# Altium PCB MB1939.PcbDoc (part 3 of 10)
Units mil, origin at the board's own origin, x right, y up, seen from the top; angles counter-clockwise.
Board outline 5910.64 x 4335.93 mil, 6 copper layers (Top Layer, l2_GND, L3_SIG, L4_VCC, L5_GND, Bottom Layer), stack 58.424 mil thick; 635 components, 489 nets, 2289 pads, 1388 vias.
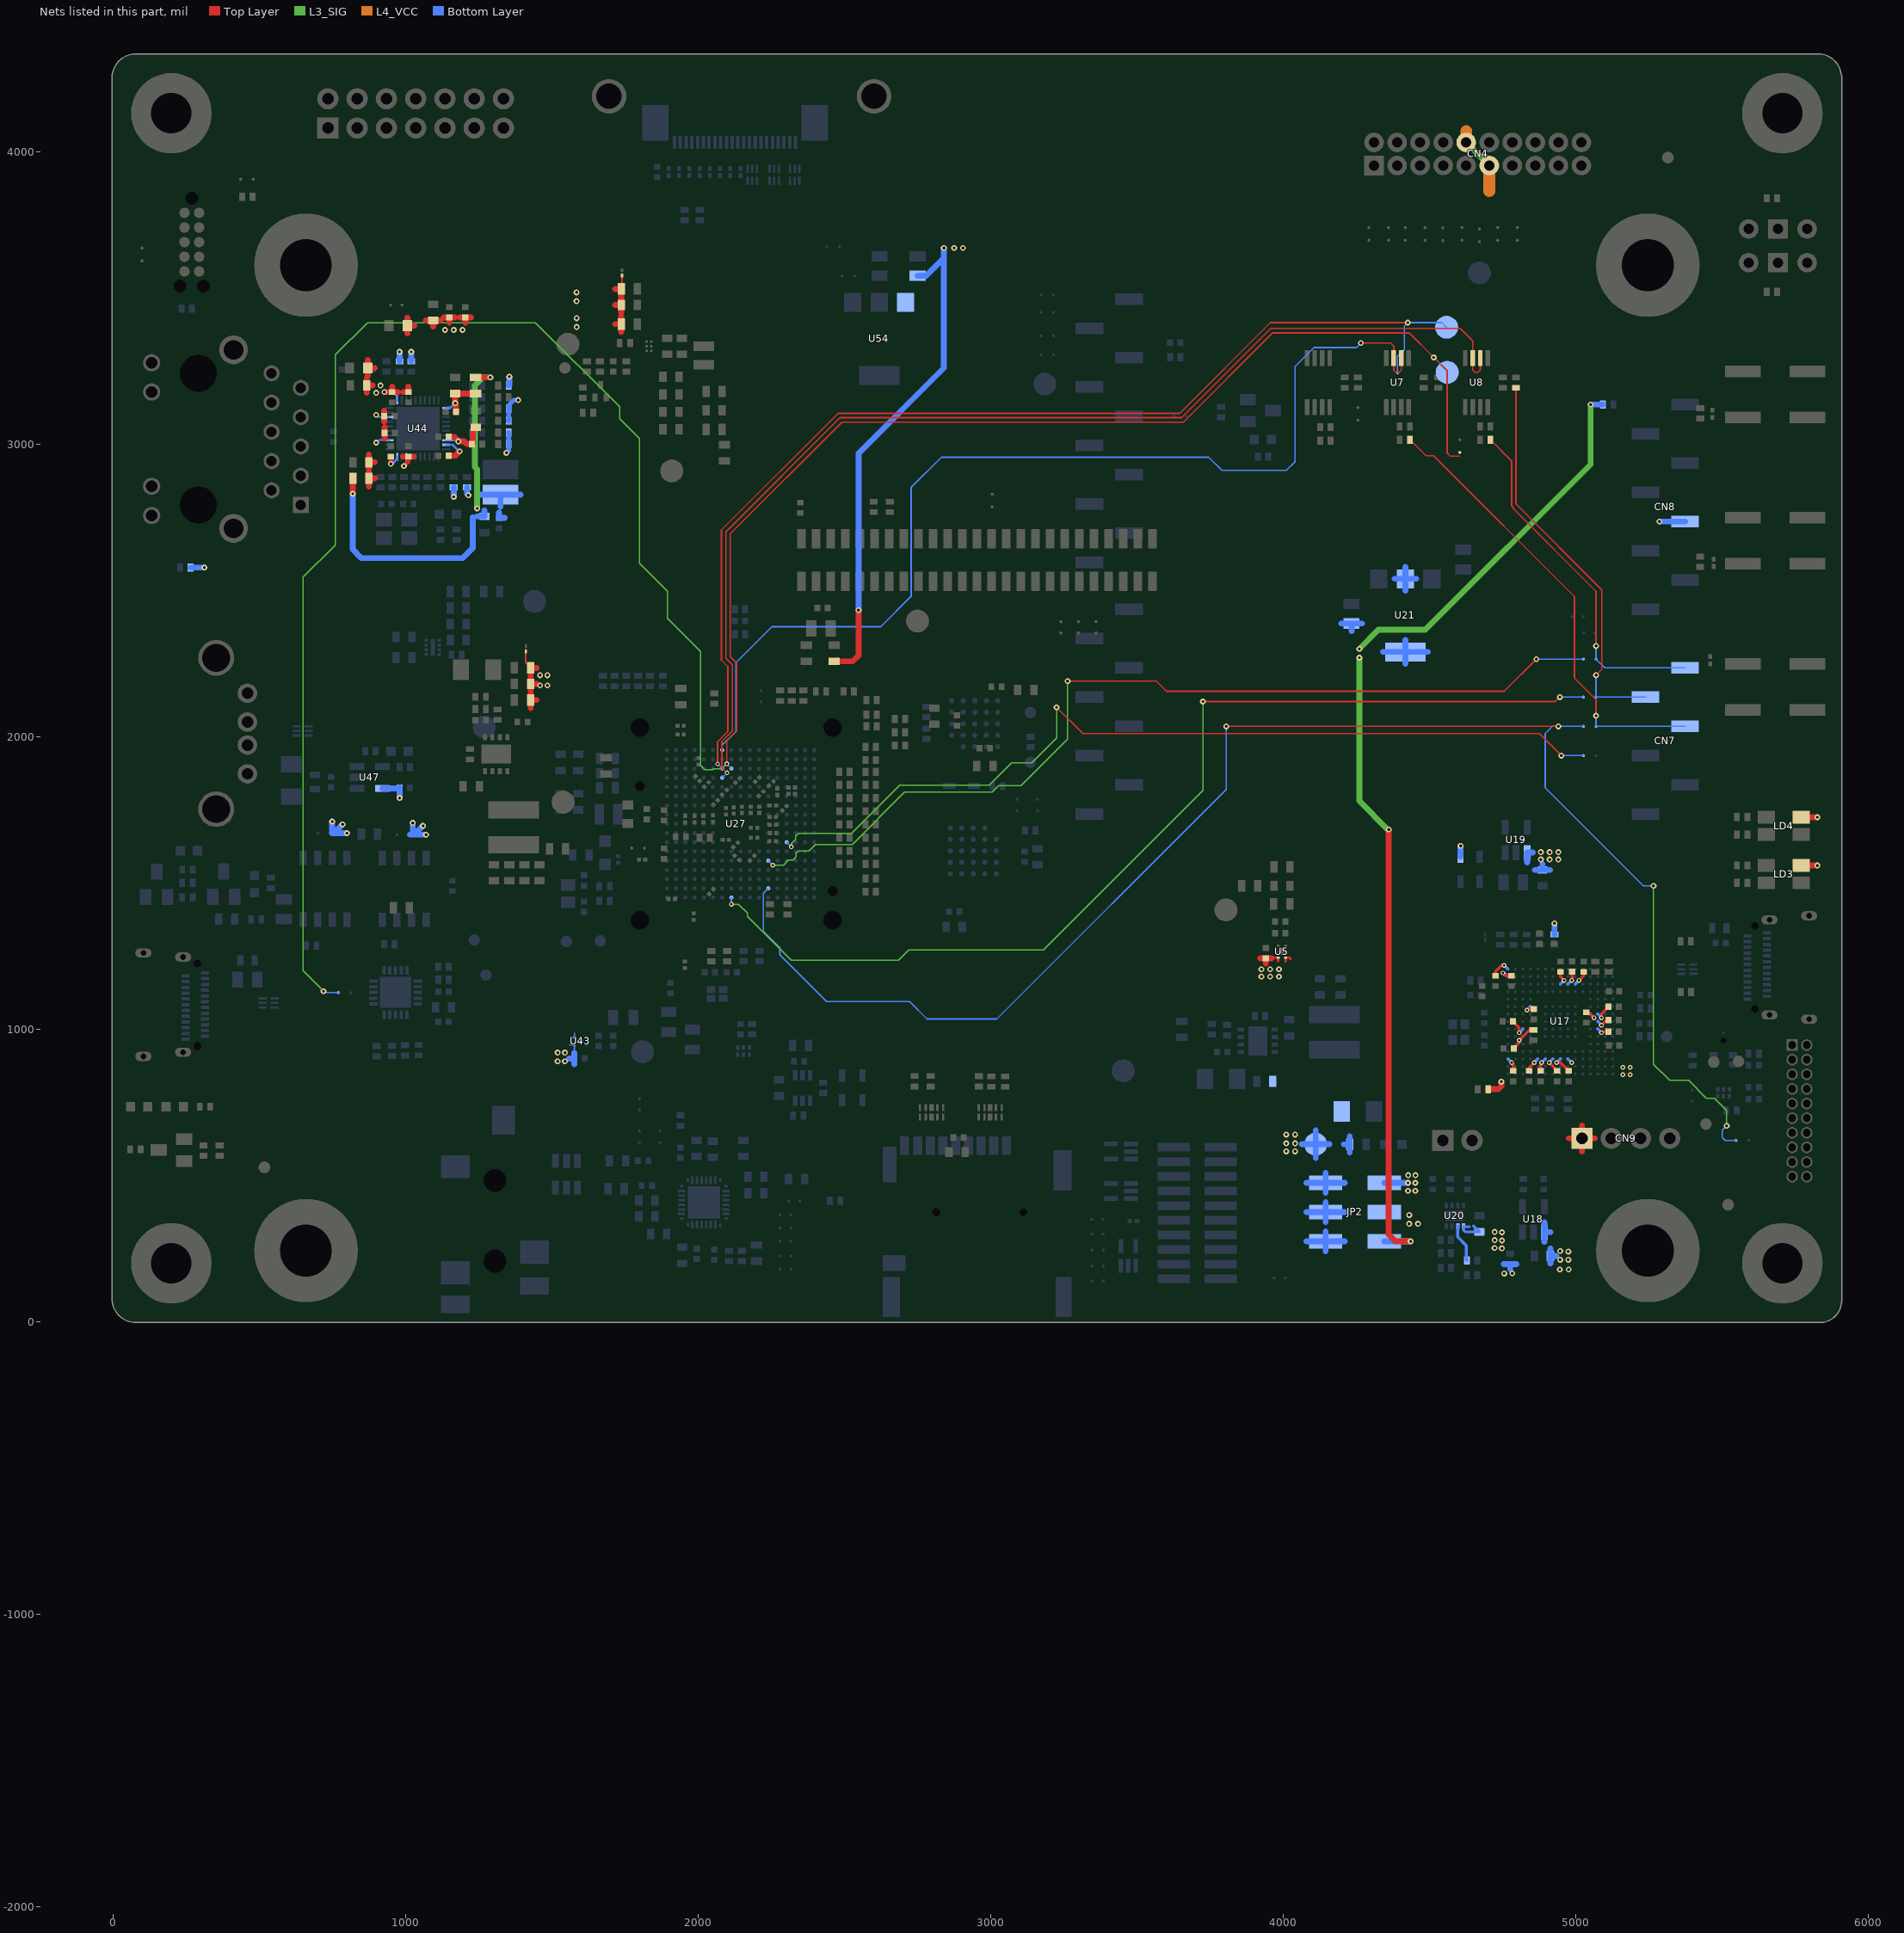
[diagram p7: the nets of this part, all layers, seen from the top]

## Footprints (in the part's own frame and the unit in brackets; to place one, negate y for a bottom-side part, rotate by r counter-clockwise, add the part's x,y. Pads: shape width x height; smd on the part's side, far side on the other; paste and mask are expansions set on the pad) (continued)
REG_XDFN4-EPAD_CASE-711AJ_1X1_H0P4_P065 [mm] "MCD-01613"
  rect 0.26x0.17 smd paste-10 mask-10: 1(-0.325,-0.515) 2(0.325,-0.515) 3(0.325,0.515) 4(-0.325,0.515)
  rect 0.52x0.52 smd rot 45 paste+0 mask+0.038: 5(0,0)
  Top Layer region: 0.455,-0.6 0.195,-0.6 0.195,-0.39 0.375,-0.21 0.455,-0.21
  Top Layer region: -0.455,-0.6 -0.195,-0.6 -0.195,-0.39 -0.375,-0.21 -0.455,-0.21
  Top Layer region: 0.455,0.6 0.195,0.6 0.195,0.39 0.375,0.21 0.455,0.21
  Top Layer region: -0.455,0.6 -0.195,0.6 -0.195,0.39 -0.375,0.21 -0.455,0.21
  silkscreen extent -0.63,-0.67 0.5,0.5, body extent -0.5,-0.5 0.5,0.5, height 0.44
SOLDER-BRIDGE_R0402-0R [mil] "MCD-01619"
  round 10 smd paste-393.7: 1(-17.72,0) 2(20.67,0)
  Top Layer region: -30.51,-13.78 -30.51,13.78 -8.37,13.78 -1.48,0 -8.37,-13.78
  Top Layer region: 1.48,13.78 8.37,0 1.48,-13.78 30.51,-13.78 30.51,13.78
  silkscreen extent -33,-17 33,17, body extent -20,-12 20,12, height 14
SOLDER-BRIDGE_R0603-0R [mil]
  round 10 smd paste-393.7: 1(-19.68,0) 2(23.62,0)
  Top Layer region: -5.91,19.69 13.78,0 -5.91,-19.68 47.24,-19.68 47.24,19.69 -5.91,19.69
  Top Layer region: -47.24,-19.68 -47.24,19.69 -15.75,19.69 3.94,0 -15.75,-19.68 -47.24,-19.68
  silkscreen extent -50,-23 50,23, body extent -36,-20 36,20, height 22
STICKER_BOARD_25X9 [mil] "Sticker to mention board CPN code"
  silkscreen extent -492,-177 492,177
STICKER_PRODUCT_25X9 [mil] "Sticker to mention board CPN code"
  silkscreen extent -492,-177 492,177
SWI_C&K_KSC321JLFS_BLACK [mm] "MCD-01799"
  rect 3.1x1 smd mask+0.05: 1(-2.8,2) 2(2.8,2) 3(-2.8,-2) 4(2.8,-2)
  silkscreen extent -3.25,-3.25 3.25,3.25, body extent -3.4,-3.25 3.4,3.25, height 3.5
SWI_C&K_KSC721JLFS_BLUE [mm] "MCD-01800"
  rect 3.1x1 smd mask+0.05: 1(-2.8,2) 2(2.8,2) 3(-2.8,-2) 4(2.8,-2)
  silkscreen extent -3.25,-3.25 3.25,3.25, body extent -3.4,-3.25 3.4,3.25, height 4.3
SWI_EAO_09-03290-01_EXTENDED_STRAIGHT_BLACK [mm]
  rect 1.7x1.7 hole 0.9 mask+0.05: 1(0,0)
  round 1.7 hole 0.9 mask+0.05: 2(0,-2.54) 3(0,2.54)
  silkscreen extent -1.25,-5 1.25,5, body extent -1.25,-5 1.25,5, height 7.9
TP_SMD_1MM [mm]
  round 1 smd paste-10 mask+0.05: 1(0,0)
  silkscreen extent -0.7,-0.7 0.7,0.7
TP_SMD_2MM [mm]
  round 2 smd paste-10 mask+0.05: 1(0,0)
  silkscreen extent -1.2,-1.2 1.2,1.2

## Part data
B1: library part MCD-01799, "Switch tactile, SPST-NO, 32V, 50mA, 6.2x6.2mm", Manufacturer=C&K, Manufacturer_HQ_COO=Unknown, Manufacturer_Part_Number=KSC321JLFS, Package=6.2x6.2mm
B2 B4: library part MCD-01800, "Switch tactile, SPST-NO, 32V, 50mA, 6.2x6.2mm", Manufacturer=C&K, Manufacturer_HQ_COO=Unknown, Manufacturer_Part_Number=KSC721JLFS, Package=6.2x6.2mm
C1 C2 C9 C14 C19 C21 C22 C23 C25 C26 C27 C42 C49 C53 C56 C62 C93 C135 C136 C170 C176 C177 C178 C179 C181 C182: library part MCD-00100, "Capacitor, MLCC, 22uF, 6V3, X5R, +/-20%, 0603, T=0.8mm", Manufacturer=MURATA, Manufacturer_Part_Number=GRM188R60J226MEA0J, Package=0603
C3 C4 C5 C6 C7 C8 C10 C11 C12 C13 C17 C18 C81 C83 C86 C87 C89 C90 C96 C97 C98 C99 C100 C101 C102 C104 C106 C107 C108 C109 C110 C111 C112 C113 C114 C117 C119 C130 C140 C142 C144 C149 C152 C159 C162 C164 C165 C180 C193 C194: library part MCD-00006, "Capacitor, MLCC, 100nF, 16V, X7R, +/-10%, 0402, T=0.5mm", Manufacturer=YAGEO, Manufacturer_Part_Number=CC0402KRX7R7BB104, Package=0402
C15 C138 C195 C201: library part MCD-00104, "Capacitor, MLCC, 220uF, 6V3, X5R, +/-20%, 1206, T=1.6mm", Manufacturer=MURATA, Manufacturer_Part_Number=GRM31CR60J227ME11, Package=1206
C16 C31 C32 C123 C124 C129 C137 C146 C183 C189: library part MCD-00099, "Capacitor, MLCC, 10uF, 10V, X5R, +/-10%, 0603, T=0.8mm", Manufacturer=MURATA, Manufacturer_Part_Number=GRM188R61A106KE69D, Package=0603
C20: library part MCD-01783, "Capacitor, MLCC, 22pF, 50V, NPO,+/-2%, 0402, T=0.5mm", Manufacturer=YAGEO, Manufacturer_Part_Number=CC0402GRNPO9BN220, Package=0402
C24 C92 C94 C95 C118 C139 C145 C161 C171 C172 C173: library part MCD-00095, "Capacitor, MLCC, 1uF, 25V, X5R, +/-10%, 0402, T=0.5mm", Manufacturer=MURATA, Manufacturer_Part_Number=GRM155R61E105KA12, Package=0402
C28 C36 C39 C40 C46 C47 C48 C50 C52 C54 C55 C58 C59 C64 C66 C67 C71 C72 C73 C74 C75 C76 C77 C78 C79 C80 C169: library part MCD-01535, "Capacitor, MLCC,100nF, 10V, X5R, +/-10%, 0201, T=0.3mm", Manufacturer=MURATA, Manufacturer_Part_Number=GRM033R61A104KE15, Package=0201
C29 C35: library part MCD-01355, "Capacitor, MLCC, 10uF, 4V, X5R, +/-20%, 0402, T=0.5mm", Manufacturer=MURATA, Manufacturer_Part_Number=GRM155R60G106ME44, Package=0402
C30 C120: library part MCD-00205, "Capacitor, MLCC, 100pF, 50V, NPO, +/-5%, 0402, T=0.5mm", Manufacturer=YAGEO, Manufacturer_Part_Number=CC0402JRNPO9BN101, Package=0402
C33 C198: library part MCD-00011, "Capacitor, MLCC, 10nF, 16V, X7R, +/-10%, 0402, T=0.5mm", Manufacturer=YAGEO, Manufacturer_Part_Number=CC0402KRX7R7BB103, Package=0402
C34: library part MCD-01356, "Capacitor, MLCC, 4.7uF, 6V3, X5R, +/-20%, 0402, T=0.5mm", Manufacturer=MURATA, Manufacturer_Part_Number=GRM155R60J475ME47, Package=0402
C37: library part MCD-02620, "Capacitor, MLCC, 2.2nF, 50V, X7R, +/-10%, 0402, T=0.5mm", Manufacturer=YAGEO, Manufacturer_Part_Number=CC0402KRX7R9BB222, Package=0402
C38 C41 C43 C44 C45 C51 C57 C60 C61 C63 C65 C68 C69 C70: library part MCD-02377, "Capacitor, MLCC, 1uF, 6.3V, X5R, +/-20%, 0201, T=0,3mm", Manufacturer=MURATA, Manufacturer_Part_Number=GRM033R60J105MEA2, Package=0201
C82 C131 C134 C199 C200: library part MCD-00014, "Capacitor, MLCC, 10uF, 25V, X5R, +/-10%, 0805, T=0.85mm", Manufacturer=YAGEO, Manufacturer_Part_Number=CC0805KRX5R8BB106, Package=0805
C84 C85 C88 C91 C141 C143 C147 C150 C158 C168: library part MCD-00009, "Capacitor, MLCC, 4.7uF, 16V, X5R, +/-10%, 0603, T=0.8mm", Manufacturer=YAGEO, Manufacturer_Part_Number=CC0603KRX5R7BB475, Package=0603
C103 C105 C133 C184: library part MCD-02198, "Capacitor, MLCC, 10nF, 50V, X7R, +/-10%, 0402, T=0.5mm", Manufacturer=YAGEO, Manufacturer_Part_Number=CC0402KRX7R9BB103, Package=0402
C115 C116 C121: library part MCD-02606, "Capacitor, MLCC, 2.2uF, 6.3V, X5R, +/-10%, 0402, T=0.5mm", Manufacturer=YAGEO, Manufacturer_Part_Number=CC0402KRX5R5BB225, Package=0402
C122: library part MCD-00016, "Capacitor, MLCC, 20pF, 50V, NPO, +/- 5%, 0402, T=0.5mm", Manufacturer=YAGEO, Manufacturer_Part_Number=CC0402JRNPO9BN200, Package=0402
C125 C132 C190: library part MCD-02355, "Capacitor, MLCC, 100nF, 25V, X7R, +/-10%, 0402, T=0.5mm", Manufacturer="WALSIN TECHNOLOGY CORPORATION", Manufacturer_Part_Number=0402B104K250CT, Package=0402
C126 C197: library part MCD-02372, "Capacitor, MLCC, 2.2uF, 25V, X7R, +/-10%, 0805, T=1,25mm", Manufacturer=MURATA, Manufacturer_Part_Number=GRM21BR71E225KE11L, Package=0805
C127 C128: library part MCD-01374, "Capacitor, MLCC, 5.6pF, 50V, NPO, +/-0.1pF, 0402, T=0.5mm", Manufacturer=YAGEO, Manufacturer_Part_Number=CC0402BRNPO9BN5R6, Package=0402
C148 C160 C163 C167: library part MCD-00012, "Capacitor, MLCC, 2.2uF, 10V, X5R, +/- 10%, 0603, T=0.8mm", Manufacturer=YAGEO, Manufacturer_Part_Number=CC0603KRX5R6BB225, Package=0603
C151: library part MCD-00015, "Capacitor, MLCC, 10pF, 50V, NPO, +/-5%, 0402, T=0.5mm", Manufacturer=YAGEO, Manufacturer_Part_Number=CC0402JRNPO9BN100, Package=0402
C153 C155: library part MCD-01932, "Capacitor, MLCC, 8.2pF, 50V, NPO, +/-0.25pF, 0402, T=0.5mm", Manufacturer=YAGEO, Manufacturer_Part_Number=CC0402CRNPO9BN8R2, Package=0402
C154 C156: library part MCD-00010, "Capacitor, MLCC, 1uF, 16V, X5R, +/-10%, 0603, T=0.8mm", Manufacturer=YAGEO, Manufacturer_Part_Number=CC0603KRX5R7BB105, Package=0603
C174 C175: library part MCD-01775, "Capacitor, MLCC, 3.3pF, 50V, NPO, +/-0.1pF, 0402, T=0.5mm", Manufacturer=YAGEO, Manufacturer_Part_Number=CC0402BRNPO9BN3R3, Package=0402
C185: library part MCD-01099, "Capacitor, MLCC, 100nF, 50V, X7R, +/-10%, 0603, T=0.8mm", Manufacturer=YAGEO, Manufacturer_Part_Number=CC0603KRX7R9BB104, Package=0603
C186 C187: library part MCD-01579, "Capacitor, MLCC, 330pF, 50V, NPO, +/-5%, 0402, T=0.5mm", Manufacturer=YAGEO, Manufacturer_Part_Number=CC0402JRNPO9BN331, Package=0402
C188 C191: library part MCD-01781, "Capacitor, MLCC, 6.8pF, 50V, NPO, +/-0.1pF, 0402, T=0.5mm", Manufacturer=YAGEO, Manufacturer_Part_Number=CC0402BRNPO9BN6R8, Package=0402
C196: library part MCD-01549, "Capacitor, MLCC, 1nF, 50V, X7R,+/-10%, 0805, T=0.6mm", Manufacturer=YAGEO, Manufacturer_Part_Number=CC0805KRX7R9BB102, Package=0805
CN1: library part MCD-00031, "Header_Plug-of-nails, 5x2, 1.27mm, No legs", Manufacturer=N/A
CN2: library part MCD-02123, "Header, 7x2, 2.54mm, VR, TH, T=5.84mm/2.54mm", Manufacturer=SAMTEC, Manufacturer_Part_Number=TSW-107-07-G-D
CN3: library part MCD-01222, "Socket, 25x2, 1.27mm, SMD, VR, T=4.55mm", Manufacturer=SAMTEC, Manufacturer_Part_Number=FLE-125-01-G-DV
CN4: library part MCD-00309, "Socket, 10x2, 2mm, RA, TH, T=6.35mm/2.29mm", Manufacturer=SAMTEC, Manufacturer_Part_Number=SQT-110-01-F-D-RA
CN5: library part MCD-00147, "Socket, 10x2, 1.27mm, VR, TH, T=4.30mm/2.40mm", Manufacturer="AMPHENOL CS", Manufacturer_Part_Number=20021311-00020T4LF
CN6 CN18: library part MCD-03232, "USB_TypeC, 24 pins, RA, SMD, T=2.96mm", Manufacturer="AMPHENOL CS", Manufacturer_Part_Number=12401826E412A
CN7: library part MCD-00299, "Socket, 6x1, 2.54mm, VR, SMD, T=9.78mm", Manufacturer=SAMTEC, Manufacturer_Part_Number=SSW-106-22-L-S-VS
CN8 CN11: library part MCD-00300, "Socket, 8x1, 2.54mm, VR, SMD, T=9.78mm", Manufacturer=SAMTEC, Manufacturer_Part_Number=SSW-108-22-L-S-VS
CN9: library part MCD-00029, "Header, 4x1, 2.54mm, VR, TH, T=5.84mm/2.54mm", Manufacturer=SAMTEC, Manufacturer_Part_Number=TSW-104-07-G-S
CN10: library part MCD-00557, "Header, 10x2, 1.27mm, VR, SMD, T=3.05mm", Manufacturer=SAMTEC, Manufacturer_Part_Number=FTSH-110-01-L-DV
CN12: library part MCD-00301, "Socket, 10x1, 2.54mm, VR, SMD, T=9.78mm", Manufacturer=SAMTEC, Manufacturer_Part_Number=SSW-110-22-L-S-VS
CN13: library part MCD-00023, "Connector_uSD Card, Reversed-Type, Mnt Push-Push", Manufacturer=YAMAICHI, Manufacturer_Part_Number=PJS008-2003-1
CN14: library part MCD-03600, "Socket_FFC/FPC, 22pins, 0.5mm, RA, SMD, T=2mm", Manufacturer="TE CONNECTIVITY"
CN15: library part MCD-00263, "Jack_ Socket-Stereo, 3.5mm, 4 pins, RA, SMD, T=5mm", Manufacturer=QIAOD, Manufacturer_Part_Number=PJ-3028B-4P
CN16: library part MCD-01129, "Connector_RJ45, With Gigabit magnetics Mag and LED, 10pins, 2.54mm, VR, TH, T= 13.84mm", Manufacturer="YUAN DEAN SCIENTIFIC", Manufacturer_Part_Number=48F-01GYDXNL, Package=13.84x21.59mm
CN17: library part MCD-01475, "USB_TypeA, RA, TH, T= 7.73mm (USB certified)", Manufacturer=MOLEX, Manufacturer_Part_Number=67643-3911
D1 D2: library part MCD-03011, "Diode, Schottky, 0V54, 1A, 23V, SOD-323", Manufacturer=STMICROELECTRONICS, Manufacturer_Part_Number=BAT20JFILM, Package=SOD-323
D4 D5 D6 D7: library part MCD-00034, "Diode, Schottky, 0V53, 1A, 10V, SOD323", Manufacturer=STMICROELECTRONICS, Manufacturer_HQ_COO=EU, Package=SOD323
H1 H2 H7 H8: library part MCD-00328, "POSITION HOLE, C7D3R5", Manufacturer=N/A, Manufacturer_HQ_COO=Unknown
H3 H4 H5 H6: library part MCD-01612, "POSITION HOLE, C9D4R5", Manufacturer=N/A
HW1: library part MCD-00547, "Sticker product, 25x9mm", Manufacturer=N/A, Manufacturer_HQ_COO=Unknown
HW2: library part MCD-00235, "Sticker Board, 25x9mm", Manufacturer=N/A
JP1: library part MCD-00045, "Header, 2x1, 2.54mm, VR, TH, T=5.84mm/2.54mm", Manufacturer=SAMTEC, Manufacturer_Part_Number=TSW-102-07-G-S
JP2: library part MCD-03177, "Header, 3x2, 2.54mm, VR, SMD, T=9,65mm", Manufacturer=SAMTEC, Manufacturer_Part_Number=TSM-103-01-G-DV
L1 L2: library part MCD-00094, "Ferrite bead, 100R @ 100MHz, +/-25%, 2000mA, 0R045, 0603, T=0.5mm", Manufacturer=MURATA, Manufacturer_Part_Number=BLM18EG101TN1, Package=0603
L3 L6: library part MCD-02242, "Inductor, 2.2uH, +/-30%, 3,83A, 0R023, 4x4mm, T=2.5mm", Manufacturer="WURTH ELEKTRONIK", Manufacturer_Part_Number=74404043022A, Package=4x4mm
L4: library part MCD-03222, "Inductor, 2.2nH, +/-0.5nH, Irat=1.4Amax, 0R018, 0603, T=1mm, Qmin=25", Manufacturer=MURATA, Manufacturer_Part_Number=LQW18AN2N2D10D, Package=0603
L5: library part MCD-02477, "Inductor, 240nH, +/-20%, 4.4A, 23mR, 0806, T=1.2mm", Manufacturer=MURATA, Manufacturer_Part_Number=DFE201612P-R24M{}P2, Package=0806
L7: library part MCD-01491, "Inductor, 1uH, +/-20%, Itemp= 2700mA, Isat= 3300mA, 0R054, 0806, T=1mm", Manufacturer=MURATA, Manufacturer_Part_Number=DFE201612P-1R0M, Package=0806
L8: library part MCD-03956, "Ferrite bead, 18R @ 100MHz, 750mA, 0R004, 0603, T=1mm", Manufacturer="TAIYO YUDEN", Manufacturer_Part_Number=LSMCA160808T180NGR, Package=0603
LD1 LD5 LD6 LD7 LD9: library part MCD-00588, "LED, Green, 2V, 20mA, 0603", Manufacturer="OSRAM OPTO SEMICONDUCTORS", Manufacturer_Part_Number="LG Q396-PS-35", Package=0603
LD2 LD8 LD10: library part MCD-00587, "LED, Red, 2V, 20mA, 0603", Manufacturer=VISHAY, Manufacturer_Part_Number=VLMS1300-GS08, Package=0603
LD3 LD4: library part MCD-02631, "LED Bicolor, Red/Green, 2V, 20mA, 4-PLCC", Manufacturer="WURTH ELEKTRONIK", Manufacturer_Part_Number=150141SV73110, Package=4-PLCC
LE1: library part MCD-00048, "Inductor, 4.7uH, +/-30%, 1A, 180mR, 1210, T=1.7mm", Manufacturer=MURATA, Manufacturer_Part_Number=LQH32PN4R7NN0L, Package=1210
LNK1 LNK2 LNK3: library part MCD-02777, "Track link on PCB 200um width for layout routing", Manufacturer=N/A
Q1 Q5 Q6: library part MCD-00073, "Transistor, NPN, 40V, 800mA, SOT23", Manufacturer="ON SEMICONDUCTOR", Manufacturer_Part_Number=BSR14, Package=SOT23
Q2: library part MCD-01969, "Transistor, MOSFET, N-CH, 60V, 265mA, SOT23-3", Manufacturer=NEXPERIA, Manufacturer_Part_Number=BSN20BK, Package=SOT23-3
Q3 Q4: library part MCD-02152, "Transistor, MOSFET, N-CH, 30V, 40A, PowerFLAT-8", Manufacturer=STMICROELECTRONICS, Manufacturer_HQ_COO=EU, Package=PowerFLAT-8
Q7: library part MCD-02221, "Transistor, MOSFET, N-CH, 20V, 530mA, SC89-3", Manufacturer=VISHAY, Manufacturer_Part_Number=Si1062X, Package=SC89-3
R1 R8 R99 R101 R131 R217: library part MCD-00062, "Resistor, 330R, 0402, +/-1%, 1/16W", Manufacturer=YAGEO, Manufacturer_Part_Number=RC0402FR-07330RL, Package=0402
R2 R211: library part MCD-00507, "Resistor, 680R, 0402, +/-1%, 1/16W", Manufacturer=YAGEO, Manufacturer_Part_Number=RC0402FR-07680RL, Package=0402
R3 R96 R97 R118 R120 R125 R150 R201 R210 R215: library part MCD-00059, "Resistor, 100K, 0402, +/-1%, 1/16W", Manufacturer=YAGEO, Manufacturer_Part_Number=RC0402FR-07100KL, Package=0402
R4 R73 R74 R76 R77 R213 R216: library part MCD-00063, "Resistor, 47K, 0402, +/-1%, 1/16W", Manufacturer=YAGEO, Manufacturer_Part_Number=RC0402FR-0747KL, Package=0402
R5 R26 R75 R93 R102 R103 R105 R106 R115 R119 R121 R138 R139 R140 R142 R143 R144 R151 R197 R207 R221 R222 R224 R225: library part MCD-00053, "Resistor, 10K, 0402, +/-1%, 1/16W", Manufacturer=YAGEO, Manufacturer_Part_Number=RC0402FR-0710KL, Package=0402
R6 R9 R19 R23 R41 R43 R130 R145 R147 R199: library part MCD-00056, "Resistor, 0R, 0603, +/-5%, 1/10W", Manufacturer=YAGEO, Manufacturer_Part_Number=RC0603JR-070RL, Package=0603
R7: library part MCD-02232, "Resistor, 22mR, 0603, +/-1%, 1/3W", Manufacturer=PANASONIC, Manufacturer_Part_Number=ERJ-3BWFR022V, Package=0603
R10 R133 R192: library part MCD-00435, "Resistor, 24K, 0402, +/-1%, 1/16W", Manufacturer=YAGEO, Manufacturer_Part_Number=RC0402FR-0724KL, Package=0402
R11: library part MCD-02979, "Resistor, 30K, 0402, +/-0.1%, 1/16W, +/-25ppm/°C", Manufacturer=YAGEO, Manufacturer_Part_Number=RT0402BRD0730KL, Package=0402
R12 R25 R37 R39 R40 R42 R44 R45 R46 R47 R48 R49 R50 R51 R52 R53 R54 R55 R56 R57 R58 R59 R60 R61 R62 R63 R64 R65 R66 R67 R68 R69 R70 R71 R72 R104 R112 R116 R117 R137 R141 R146 R154 R155 R170 R171 R189 R198 R202 R205 R206 R226 R227: library part MCD-00052, "Resistor, 0R, 0402, +/-5%, 1/16W", Manufacturer=YAGEO, Manufacturer_Part_Number=RC0402JR-070RL, Package=0402
R13 R14 R15 R16 R17 R18 R174 R175 R176 R177 R178 R191 R194 R195: library part MCD-00065, "Resistor, 4K7, 0402, +/-1%, 1/16W", Manufacturer=YAGEO, Manufacturer_Part_Number=RC0402FR-074K7L, Package=0402
R20 R24 R188: library part MCD-03197, "Resistor, 330mR, 0603, +/-1%, 1/5W", Manufacturer=YAGEO, Manufacturer_Part_Number=PT0603FR-7W0R33L, Package=0603
R21 R22 R27 R30 R31 R78 R79 R136 R167 R173 R179 R187 R209: library part MCD-00181, "Resistor, 0R, 0603, +/- 0.5mR, 1/4W", Manufacturer="ROHM SEMICONDUCTOR", Manufacturer_Part_Number=PMR03EZPJ000, Package=0603
R28: library part MCD-00493, "Resistor, 56K, 0402, +/-1%, 1/16W", Manufacturer=YAGEO, Manufacturer_Part_Number=RC0402FR-0756KL, Package=0402
R29: library part MCD-00405, "Resistor, 160K, 0402, +/-1%, 1/16W", Manufacturer=YAGEO, Manufacturer_Part_Number=RC0402FR-07160KL, Package=0402
R32 R33 R34: library part MCD-00417, "Resistor, 200R, 0402, +/-1%, 1/16W", Manufacturer=YAGEO, Manufacturer_Part_Number=RC0402FR-07200RL, Package=0402
R35 R168: library part MCD-02233, "Resistor, 50mR, 0603, +/-1%, 1/3W", Manufacturer=PANASONIC, Manufacturer_Part_Number=ERJ-3BWFR050V, Package=0603
R36 R38 R149 R153 R186 R200 R204: library part MCD-00068, "Resistor, 1K5, 0402, +/-1%, 1/16W", Manufacturer=YAGEO, Manufacturer_Part_Number=RC0402FR-071K5L, Package=0402
R80: library part MCD-03198, "Resistor, 750mR, 0603, +/-1%, 1/5W", Manufacturer=YAGEO, Manufacturer_Part_Number=PT0603FR-7W0R75L, Package=0603
R81 R84 R85 R88 R89 R92: library part MCD-00483, "Resistor, 470K, 0402, +/-1%, 1/16W", Manufacturer=YAGEO, Manufacturer_Part_Number=RC0402FR-07470KL, Package=0402
R82 R83 R86 R87 R90 R91: library part MCD-00495, "Resistor, 560K, 0402, +/-1%, 1/16W", Manufacturer=YAGEO, Manufacturer_Part_Number=RC0402FR-07560KL, Package=0402
R94 R95 R114 R122: library part MCD-00455, "Resistor, 33R, 0402, +/-1%, 1/16W", Manufacturer=YAGEO, Manufacturer_Part_Number=RC0402FR-0733RL, Package=0402
R98 R100: library part MCD-02665, "Resistor, 1K, 0402, +/-0.1%, 1/16W, +/-25ppm/°C", Manufacturer=YAGEO, Manufacturer_Part_Number=RT0402BRD071KL, Package=0402
R107 R108 R113: library part MCD-00333, "Resistor, 5K1, 0402, +/-1%, 1/16W", Manufacturer=YAGEO, Manufacturer_Part_Number=RC0402FR-075K1L, Package=0402
R109 R124: library part MCD-00185, "Resistor, 3K, 0402, +/-1%, 1/16W", Manufacturer=YAGEO, Manufacturer_Part_Number=RC0402FR-073KL, Package=0402
R110: library part MCD-00067, "Resistor, 100R, 0402, +/- 1%, 1/16W", Manufacturer=YAGEO, Manufacturer_Part_Number=RC0402FR-07100RL, Package=0402
R111: library part MCD-00061, "Resistor, 1K, 0402, +/-1%,1/16W", Manufacturer=YAGEO, Manufacturer_Part_Number=RC0402FR-071KL, Package=0402
R123 R128: library part MCD-02455, "Resistor, 3K9, 0402, +/-1%, 1/16W, +/-100ppm/°C", Manufacturer=YAGEO, Manufacturer_Part_Number=RC0402FR-073K9L, Package=0402
R126: library part MCD-00381, "Resistor, 1K3, 0402, +/-1%, 1/16W", Manufacturer=YAGEO, Manufacturer_Part_Number=RC0402FR-071K3L, Package=0402
R127: library part MCD-00409, "Resistor, 1K8, 0402, +/-1%, 1/16W", Manufacturer=YAGEO, Manufacturer_Part_Number=RC0402FR-071K8L, Package=0402
R129: library part MCD-00528, "Resistor, 820R, 0603, +/-1%, 1/10W", Manufacturer=YAGEO, Manufacturer_Part_Number=RC0603FR-07820RL, Package=0603
R132: library part MCD-00489, "Resistor, 560R, 0402, +/-1%, 1/16W", Manufacturer=YAGEO, Manufacturer_Part_Number=RC0402FR-07560RL, Package=0402
R134 R223: library part MCD-00182, "Resistor, 1M, 0402, +/-1%, 1/16W", Manufacturer=YAGEO, Manufacturer_Part_Number=RC0402FR-071ML, Package=0402
R135: library part MCD-00521, "Resistor, 75K, 0402, +/-1%, 1/16W", Manufacturer=YAGEO, Manufacturer_Part_Number=RC0402FR-0775KL, Package=0402
R148 R159 R163: library part MCD-00179, "Resistor, 0R, 0805, +/-5%, 1/8W", Manufacturer=YAGEO, Manufacturer_Part_Number=RC0805JR-070RL, Package=0805
R152: library part MCD-02335, "Resistor, 140K, 0402, +/-1%, 1/16W", Manufacturer=YAGEO, Manufacturer_Part_Number=RC0402FR-07140KL, Package=0402
R156: library part MCD-00057, "Resistor, 2K2, 0402, +/-1%, 1/16W", Manufacturer=YAGEO, Manufacturer_Part_Number=RC0402FR-072K2L, Package=0402
R157: library part MCD-04136, "Resistor, 422K, 0402, +/-1%, 1/16W", Manufacturer=YAGEO, Manufacturer_Part_Number=RC0402FR-07422KL, Package=0402
R158: library part MCD-00165, "Resistor, 150K, 0402, +/-1%, 1/16W", Manufacturer=YAGEO, Manufacturer_Part_Number=RC0402FR-07150KL, Package=0402
R160 R161 R162 R166 R169 R172 R180 R181 R182 R183 R184 R185 R196 R203: library part MCD-00189, "Resistor, 22R, 0402, +/-1%, 1/16W", Manufacturer=YAGEO, Manufacturer_Part_Number=RC0402FR-0722RL, Package=0402
R164 R165: library part MCD-00345, "Resistor, 20R, 0603, +/-1%, 1/10W", Manufacturer=YAGEO, Manufacturer_Part_Number=RC0603FR-0720RL, Package=0603
R190 R218 R219: library part MCD-00064, "Resistor, 510R, 0402, +/-1%, 1/16W", Manufacturer=YAGEO, Manufacturer_Part_Number=RC0402FR-07510RL, Package=0402
R193: library part MCD-02265, "Resistor,100K,0402,0.5%,1/16W", Manufacturer=YAGEO, Manufacturer_Part_Number=RC0402DR-07100KL, Package=0402
R208: library part MCD-00183, "Resistor, 2K49, 0402, +/-1%, 1/16W", Manufacturer=YAGEO, Manufacturer_Part_Number=RC0402FR-072K49L, Package=0402
R212: library part MCD-00441, "Resistor, 270R, 0402, +/-1%, 1/16W", Manufacturer=YAGEO, Manufacturer_Part_Number=RC0402FR-07270RL, Package=0402
R214: library part MCD-00430, "Resistor, 22K, 0603, +/-1%, 1/10W", Manufacturer=YAGEO, Manufacturer_Part_Number=RC0603FR-0722KL, Package=0603
R220: library part MCD-03930, "Resistor, 2R, 0402, +/-1%, 1/16W", Manufacturer=YAGEO, Manufacturer_Part_Number=RC0402FR-072RL, Package=0402
R228 R229: library part MCD-00387, "Resistor, 1M3, 0402, +/-1%, 1/16W", Manufacturer=YAGEO, Manufacturer_Part_Number=RC0402FR-071M3L, Package=0402
SB1 SB2 SB4 SB5 SB9 SB10 SB11 SB12 SB13 SB14 SB15 SB16 SB17 SB18 SB20 SB21 SB22 SB23 SB25 SB31 SB32 SB33 SB34 SB41 SB45 SB46 SB47 SB48 SB49 SB51 SB53: library part MCD-00071, "Resistor, 0R, SB0603, 5%, 0.1W", Manufacturer=YAGEO, Manufacturer_HQ_COO=Unknown, Manufacturer_Part_Number=RC0603JR-070RL, Package=0603
SB3 SB6 SB7 SB8 SB19 SB26 SB27 SB28 SB29 SB30 SB35 SB36 SB37 SB38 SB39 SB40 SB42 SB43 SB44 SB54 SB55 SB56 SB57 SB58 SB59: library part MCD-01618, "Resistor, 0R, SB0402, 5%, 0.063W", Manufacturer=YAGEO, Manufacturer_Part_Number=RC0402JR-070RL, Package=0402
SW1 SW2: library part MCD-00566, "Switch slide, SPDT, 24V, 500mA, 2.5x10mm", Manufacturer=EAO, Manufacturer_HQ_COO=Unknown, Manufacturer_Part_Number=09.03290.01, Package=2.5x10mm
TP1 TP3 TP4 TP5 TP10 TP11 TP12 TP13 TP14 TP15 TP16 TP17 TP21 TP22: library part MCD-00177, "Test Point, SMD, 2mm", Manufacturer=N/A
TP2 TP6 TP7 TP8 TP9 TP18 TP19 TP20 TP23 TP24 TP25: library part MCD-00074, "Test Point, SMD, 1mm", Manufacturer=N/A, Manufacturer_HQ_COO=Unknown
U1 U22: library part MCD-02243, "Regulator, 3A, DC step-down switching", Manufacturer=STMICROELECTRONICS, Manufacturer_HQ_COO=EU, Package=VFDFPN-8
U2: library part MCD-02469, "IC, 2V4 to 5V5 Input, Tiny 6-pin, 3A, Step-Down converter in 1.2x0.8mm wafer chip scale package and suitable for embedding", Manufacturer="TEXAS INSTRUMENTS", Package=WCSP-6
U3 U4: library part MCD-00667, "Diode, ESD protection, 3V6, 100nA, 5V8, uQFN-10", Manufacturer=STMICROELECTRONICS, Manufacturer_HQ_COO=EU, Package=uQFN-10
U5: library part MCD-02222, "LDO, 200mA, Very low quiescent current linear regulator IC", Manufacturer=STMICROELECTRONICS, Manufacturer_HQ_COO=EU, Manufacturer_Part_Number=LD39020ADTPU33R, Package=DFN-4
U6 U7 U8: library part MCD-00325, "Operational Amplifier, Single/dual/quad rail-to-rail input/output, 5V5, 400KHz", Manufacturer=STMICROELECTRONICS, Manufacturer_HQ_COO=EU, Package=miniSO-8
U9 U10 U12 U33 U35 U36 U37 U38 U39 U40 U41 U53: library part MCD-00170, "Diode, ESD TVS, 3V, 100nA, 8V, ST0201", Manufacturer=STMICROELECTRONICS, Manufacturer_HQ_COO=EU, Manufacturer_Part_Number=ESDALC6V1-1U2, Package=ST0201
U13: library part MCD-02122, "MEMS, Audio sensor Multi performance mode digital microphone", Manufacturer=STMICROELECTRONICS, Manufacturer_HQ_COO=EU, Manufacturer_Part_Number=MP23DB01HPTR, Package=RHLGA-5
U14 U32: library part MCD-02386, "Analog Switch, Low-ohmic single-pole double-throw analog switch", Manufacturer=NXP, Manufacturer_Part_Number=NX3L1T3157GMZ, Package=SOT886-6
U15 U29 U30 U31 U49 U51: library part MCD-03060, "IC, ESD protection and Common Filter High Speed serial Interfaces, 10.7 GHz", Manufacturer=STMICROELECTRONICS, Package=uQFN-6
U16 U50: library part MCD-01207, "Diode, ESD TVS, 22V, 200nA, 25V8, QFN1610", Manufacturer=STMICROELECTRONICS, Manufacturer_HQ_COO=EU, Manufacturer_Part_Number=ESDA25P35-1U1M, Package=QFN1610
U17: library part MCD-03851, "MCU, ARM Cortex-M7 32-bit, 512KB Flash, 276KB RAM, With Crypto", Manufacturer=STMICROELECTRONICS, Manufacturer_HQ_COO=EU, Manufacturer_Part_Number=STM32F723IEK6, Package=BGA-176
U18 U47: library part MCD-00159, "IC, Enhanced single channel power switches", Manufacturer=STMICROELECTRONICS, Package=SOT23-5
U19: library part MCD-02514, "LDO, 300mA, 28V, Low-dropout voltage, with 5uA quiescent current", Manufacturer=STMICROELECTRONICS, Package=SOT23-5
U20: library part MCD-02532, "IC, 2V7 to 18V, 4A, 34mR, eFuse with fast overvoltage protection", Manufacturer="TEXAS INSTRUMENTS", Package=WSON-8
U21: library part MCD-00088, "LDO, Adjustable and fixed low drop positive voltage regulator", Manufacturer=STMICROELECTRONICS, Manufacturer_HQ_COO=EU, Package=SOT223-4
U23 U24 U52: library part MCD-00136, "Diode, ESD Transil, 3V, 1uA, 7V2, SOT323-5", Manufacturer=STMICROELECTRONICS, Manufacturer_HQ_COO=EU, Package=SOT323-5
U25: library part MCD-02601, "Memory, Serial NOR Flash, 1V8, 1Gbit, 200MHz, BGA-24", Manufacturer=MACRONIX, Manufacturer_HQ_COO=Unknown, Package=BGA-24
U26: library part MCD-02129, "Memory, DDR PSRAM, 1V8, 256Mbit, 200MHz, BGA-24", Manufacturer="AP MEMORY TECHNOLOGY CORP.", Package=BGA-24
U27: library part MCD-03176, "Neural MCU, Arm® Cortex®-M55, 600-Gops ST Neural-ART Accelerator, Neo-Chrom 2.5D GPU, 4.2 MB contiguous SRAM", Manufacturer=STMICROELECTRONICS, Package=VFBGA264
U28: library part MCD-02311, "IC, 5V5, 1.5A, 90mR Self-Protected load switch with controlled rise time", Manufacturer="TEXAS INSTRUMENTS", Manufacturer_Part_Number=TPS22919DCKR, Package=SC70-6
U34: library part MCD-03825, "Audio Codec, Ultra Low-Power Codec for Portable Audio Applications", Manufacturer="CIRRUS LOGIC"
U42: library part MCD-00247, "Diode, ESD Transil, 5V, 1uA, 8V, SOT23-6", Manufacturer=STMICROELECTRONICS, Manufacturer_HQ_COO=EU, Package=SOT23-6
U43: library part MCD-02224, "LDO, 200mA, Very low quiescent current linear regulator IC", Manufacturer=STMICROELECTRONICS, Manufacturer_HQ_COO=EU, Manufacturer_Part_Number=LD39020ADTPU18R, Package=DFN-4
U44: library part MCD-01130, "ETHERNET Transceiver, 10/100/1000M, QFN40 , SMPS version", Manufacturer=REALTEK, Package=QFN-40
U45: library part MCD-02937, "LDO, 1A, 1V8, Fast transient, ultra-low noise", Manufacturer=STMICROELECTRONICS, Package=DFN8
U46: library part MCD-02130, "IC, USB Type-C Protection for DRP applications Dual Role Power", Manufacturer=STMICROELECTRONICS, Manufacturer_HQ_COO=EU, Package=QFN-20
U48: library part MCD-01026, "Diode, ESD TVS, 5V5, 1.5uA, 6V8, QFN1610", Manufacturer=STMICROELECTRONICS, Manufacturer_HQ_COO=EU, Manufacturer_Part_Number=ESDA7P120-1U1M, Package=QFN1610
U54: library part MCD-00089, "LDO, Adjustable and fixed low drop positive voltage regulator", Manufacturer=STMICROELECTRONICS, Manufacturer_HQ_COO=EU, Package=SOT223-4
X1: library part MCD-01036, "Crystal, 24MHz, 6pF, +/-20ppm, 80R, 2.0x1.6mm", Manufacturer=NDK, Manufacturer_Part_Number=NX2016SA-24MHZ-EXS00A-CS10820, Package=2.0x1.6mm
X2: library part MCD-02262, "Crystal, 48MHz, 7pF, +/-20 ppm, 80R, 1.6x1.2mm", Manufacturer=NDK, Manufacturer_Part_Number=NX1612SA-48MHZ-EXS00A-CS13734, Package=1.6x1.2mm
X3: library part MCD-01479, "Crystal, 32.768kHz, 6pF, +/-20ppm, 80K, 2.05x1.2mm", Manufacturer=NDK, Manufacturer_Part_Number=NX2012SA-32.768KHZ-EXS00A-MU00527, Package=2.05x1.2mm
X4: library part MCD-01463, "Crystal, 25MHz, 10pF, +/-20ppm, 50R, 3.2x2.5mm", Manufacturer=NDK, Manufacturer_Part_Number=NX3225GA-25MHZ-EXS00A-CG06750, Package=3.2x2.5mm

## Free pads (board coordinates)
  round 40 smd mask+40: 1(518,528) 1(5314,3979) 1(5520,400)
  round 40 smd far side mask+40: 1(518,528) 1(5314,3979) 1(5520,400)
  round 118.11 hole 86.61 paste-99999 mask+1.97: 1(1695.67,4188.45) 1(2601.18,4188.45)
  round 20 on Mech16: 1(2091.91,-1897.61) 1(4015.04,-1897.61)

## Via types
v1: diameter 20, hole 10, Top Layer to Bottom Layer, tented both sides, 1072 vias
v2: diameter 16, hole 8, Top Layer to Bottom Layer, tented both sides, 316 vias

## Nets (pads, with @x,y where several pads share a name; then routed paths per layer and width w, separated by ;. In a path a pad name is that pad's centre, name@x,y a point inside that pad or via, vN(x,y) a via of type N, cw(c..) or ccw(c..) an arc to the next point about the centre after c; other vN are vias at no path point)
1V05_AVDD_GMII: C2.2 C3.2 C4.2 C7.2 R6.1 U44.3 U44.8 U44.38 | length 434.4
  Top Layer w15: v1(995,2925) 1010,2940 C7.2@1010,2957.28
  Top Layer w20: 875.19,2855.12 R6.1@875.19,2882.83 ; 875.19,2910.54 R6.1@875.19,2882.83 ; 875.19,2912.29 C2.2@875.19,2937.83 ; 875.19,2963.37 C2.2@875.19,2937.83 ; 895.81,2882.83 R6.1@875.19,2882.83 ; 895.81,2937.83 C2.2@875.19,2937.83 ; 927.28,3075.95 927.28,3114.05 ; 928.45,3018.82 928.45,3056.92 ; 990.95,2957.28 C7.2@1010,2957.28 1029.05,2957.28
  Bottom Layer w5: v1(900,3005) 908.46,3013.46 U44.3@946.18,3013.46 ; v1(900,3100) 907.8,3092.2 U44.8@946.18,3092.2
  Bottom Layer w8: v1(995,2925) 1003.26,2933.26 U44.38@1003.27,2956.37
1V05_DVDD_GMII: C12.2 C14.2 R9.1 U44.21 | length 171.2
  Top Layer w20: C12.2@1172.72,3110 1172.72,3137.28 v1(1170,3140) C14.2@1170,3172.44 R9.1@1240,3172.44
  Bottom Layer w8: U44.21@1139.09,3123.7 1153.69,3123.69 v1(1170,3140)
1V05_GMII: C180.2 C181.2 LE1.2 R6.2 R9.2 | length 1584.5
  Top Layer w20: v1(820.08,2830) R6.2@820.08,2882.83 ; R9.2@1240,3227.56 v1(1290,3227.56)
  L3_SIG w20: v1(1245,2780) 1245,2914 1237.72,2921.28 1237.72,3200.28 1265,3227.56 v1(1290,3227.56)
  Bottom Layer w20: v1(820.08,2830) 820.08,2639.92 850,2610 1195,2610 1230,2645 1230,2750 ; 1244.46,2752.56 C181.2@1270,2752.56 1270,2773.18 ; 1255.95,2826.69 LE1.2@1325,2826.69 ; 1320,2765.78 C180.2@1320,2747.72 1339.05,2747.72 ; 1325,2785.2 LE1.2@1325,2826.69 ; 1394.05,2826.69 LE1.2@1325,2826.69
3V3_AVDD_GMII: C1.2 C5.2 C6.2 C8.2 L1.1 U44.11 U44.40 | length 368
  Top Layer w15: v1(950,2932.24) C5.2@950,2957.28
  Top Layer w20: 867.56,3174.46 C1.2@867.56,3200 ; 867.56,3225.54 C1.2@867.56,3200 ; 871.5,3233.28 L1.1@871.5,3260 ; 871.5,3286.72 L1.1@871.5,3260 ; 888.18,3200 C1.2@867.56,3200 ; 895.27,3260 L1.1@871.5,3260 ; v1@935.95,3177.72 C6.2@955,3177.72 ; 955,3195.78 C6.2@955,3177.72 ; 974.05,3177.72 C6.2@955,3177.72 ; 990.95,3177.72 C8.2@1010,3177.72 1010,3195.78
  Bottom Layer w8: v1(927.83,3177.83) 957.98,3177.83 971.76,3164.05 U44.11@971.77,3149.29 ; v1(950,2932.24) 955.46,2932.24 971.76,2948.54 U44.40@971.77,2956.37
  other v1: 900.16,3175 915,3200
3V3_DVDD_GMII: C9.2 C10.2 C11.2 C13.2 C17.2 C18.2 C19.1 L2.1 R174.2 R175.2 R176.2 R177.2 R178.2 R186.2 R191.1 R200.2 R204.2 R219.2 U44.28 U44.29 | length 926.7
  Top Layer w20: 1006.5,3378.28 L2.1@1006.5,3405 ; 1006.5,3431.72 L2.1@1006.5,3405 ; 1030.27,3405 L2.1@1006.5,3405 ; 1069.46,3422.44 C9.2@1095,3422.44 ; 1095,3401.82 C9.2@1095,3422.44 ; 1120.54,3422.44 C9.2@1095,3422.44 ; 1130.95,3432.28 C13.2@1150,3432.28 ; C10.2@1147.72,2960 1170,2960 v1(1185,2975) ; C11.2@1147.72,3025 1165,3025 v1(1181,3009) 1201,3009 1210,3000 C18.2@1227.29,3000 1230,3002.71 1230,3047.44 C19.1@1240,3057.44 ; 1150,3414.22 C13.2@1150,3432.28 ; 1169.05,3432.28 C13.2@1150,3432.28 ; 1185.95,3432.28 C17.2@1205,3432.28 ; 1205,3414.22 C17.2@1205,3432.28 ; 1224.05,3432.28 C17.2@1205,3432.28
  Bottom Layer w7: U44.29@1139.09,2997.71 1160.87,2997.71
  Bottom Layer w8: U44.28@1139.09,3013.46 1171.54,3013.46 1176,3009 v1(1181,3009) ; 1160.87,2997.71 1183.58,2975 v1(1185,2975)
  Bottom Layer w15: v1(1345,2970) 1352.72,2977.72 R176.2@1352.72,3000 R177.2@1352.72,3040 ; R174.2@1352.72,3080 R178.2@1352.72,3120 1352.72,3132.72 1370,3150 v1(1385,3150)
  Bottom Layer w20: R219.2@265.35,2577.83 v1(312.83,2577.83) ; R204.2@980,3282.72 v1(980,3315) ; R200.2@1020,3282.72 v1(1020,3315) ; v1(1165,2819.72) R191.1@1165,2852.28 ; R186.2@1210,2852.28 1210,2830 v1(1215,2825) ; R175.2@1352.72,3200 1355,3202.28 v1(1355,3230)
  other v1: 1135,3390 1165,3390 1195,3390
3V3_STLK: C96.1 C97.1 C98.1 C99.1 C100.1 C101.1 C102.1 C104.1 C106.1 C107.1 C108.1 C109.1 C110.1 C111.1 C112.1 C113.1 C114.1 C124.2 CN9.1 LD3.4 LD4.4 R26.2 R93.2 R120.1 U17.C1 U17.C5 U17.C6 U17.C7 U17.C8 U17.C9 U17.F3 U17.G3 U17.G13 U17.H13 U17.J12 U17.J13 U17.K4 U17.N8 U17.N9 U17.N10 U17.P1 U17.R1 U19.1 | length 1552.7
  Top Layer w10: C96.1@4725,1182.72 4725,1197.31 4746.03,1218.34 v2(4754.75,1218.34) ; v2(4750.07,1192.39) 4759.74,1182.72 C99.1@4780,1182.72 ; v2(4780.34,885.66) 4785,881 C100.1@4785,857.72 ; C97.1@4784.41,1026.42 4805.93,1004.9 v2(4805.93,988.02) ; C98.1@4787.72,935 4805.93,953.21 v2(4805.93,962.43) 4841.22,997.72 R93.2@4855,997.72 ; v2(4832.1,1065.37) 4835.87,1069.14 C102.1@4856.69,1069.14 ; C101.1@4840,857.72 4840,868.55 v2(4857.11,885.66) ; C104.1@4880,857.72 4880,882.96 v2(4882.7,885.66) ; v2(4908.29,885.66) 4935,858.95 C106.1@4935,857.72 ; v2(4933.88,885.66) 4947.06,885.66 C108.1@4975,857.72 ; C107.1@4946.69,1195.98 4946.69,1179.94 v2(4959.47,1167.16) ; v2(4985.06,1167.16) 4986.69,1168.79 C109.1@4986.69,1196.41 ; v2(5010.65,1167.16) 5026.69,1183.2 C110.1@5026.69,1195.98 ; C111.1@5035,1057.72 5043.31,1057.72 v2(5061.83,1039.2) ; v2(5087.42,988.02) 5090.82,991.42 C112.1@5111.27,991.42 ; v2(5087.42,1013.61) 5105.23,1031.42 C113.1@5111.27,1031.42 ; v2(5087.42,1039.2) 5087.42,1052.58 C114.1@5111.27,1076.42
  Top Layer w20: R26.2@4700,795 4735,795 4745,805 v1(4745,820.71) ; 4976.07,627.01 CN9.1@5020.51,627.01 ; 5020.51,582.57 CN9.1@5020.51,627.01 ; 5020.51,671.45 CN9.1@5020.51,627.01 ; 5064.95,627.01 CN9.1@5020.51,627.01 ; LD3.4@5769.06,1559.53 v1(5824.53,1559.53) ; LD4.4@5769.06,1724.53 v1(5825,1724.53)
  Bottom Layer w10: v2(4750.07,1192.39) 4755.11,1192.39 U17.P1@4767.54,1179.96 ; v2(4754.75,1218.34) U17.R1@4767.54,1205.55 ; U17.C1@4767.55,898.45 v2(4780.34,885.66) ; v2(4805.93,962.43) U17.F3@4818.74,975.24 ; v2(4805.93,988.02) U17.G3@4818.74,1000.83 ; v2(4832.1,1065.37) U17.K4@4844.33,1077.6 ; v2(4857.11,885.66) U17.C5@4869.92,898.47 ; v2(4882.7,885.66) U17.C6@4895.51,898.47 ; v2(4908.29,885.66) U17.C7@4921.1,898.47 ; v2(4933.88,885.66) U17.C8@4946.7,898.47 ; U17.N8@4946.7,1154.37 v2(4959.47,1167.16) ; U17.C9@4972.29,898.47 v2(4985.06,885.66) ; U17.N9@4972.29,1154.37 v2(4985.06,1167.16) ; U17.N10@4997.88,1154.37 v2(5010.65,1167.16) ; U17.J12@5049.04,1052 v2(5061.83,1039.2) ; U17.G13@5074.65,1000.83 v2(5087.42,988.02) ; U17.H13@5074.65,1026.42 v2(5087.42,1013.61) ; U17.J13@5074.65,1052.01 v2(5087.42,1039.2)
  Bottom Layer w20: 4753.2,197.28 R120.1@4775,197.28 ; 4775,179.22 R120.1@4775,197.28 ; 4796.8,197.28 R120.1@4775,197.28 ; 4832.91,1570.09 U19.1@4832.92,1603.7 4852.74,1603.7 ; 4859.97,1544.57 C124.2@4885.51,1544.57 ; 4885.51,1565.19 C124.2@4885.51,1544.57 ; 4911.05,1544.57 C124.2@4885.51,1544.57
  other v1: 4755,164.9 4782.3,165.3 4880,1580 4910,1580 4940,1580 4880,1605 4910,1605 4940,1605
  other v2: 5160,845 5185,845 5160,870 5185,870
5V: C23.2 C27.2 C92.2 C173.2 C190.2 C199.2 C201.2 CN4.6 CN4.15 CN8.5 D2.1 JP2.2 JP2.4 JP2.6 LNK1.2 LNK2.2 R19.1 R20.1 R23.1 R24.1 R43.1 R113.2 R129.1 R130.1 SB48.1 TP4.1 U5.3 U5.4 U43.3 U43.4 U47.5 U54.3 | length 3944.4
  Top Layer w5: LNK1.2@1412,2291.14 1412,2288.14 1411,2287.14 1411,2251.56 R20.1@1427.56,2235 ; R24.1@1737.45,3530 1740,3532.56 LNK2.2@1740,3576.14
  Top Layer w8: 3970,1245 3970.28,1244.72 U5.3@3982.21,1244.72 3982.2,1232.8 ; 4007.8,1232.2 U5.4@4007.8,1244.72 4020.28,1244.72 4025,1240
  Top Layer w20: 1427.56,2097.29 R19.1@1427.56,2125 ; 1427.56,2152.71 R19.1@1427.56,2125 ; 1427.56,2154.46 C23.2@1427.56,2180 ; 1427.56,2205.54 C23.2@1427.56,2180 ; 1427.56,2207.29 R20.1@1427.56,2235 1448.18,2235 ; 1448.18,2125 R19.1@1427.56,2125 ; 1448.18,2180 C23.2@1427.56,2180 ; 1716.82,3410 R23.1@1737.45,3410 ; 1716.82,3475 C27.2@1737.45,3475 ; 1716.82,3530 R24.1@1737.45,3530 1737.44,3502.29 ; 1737.44,3382.29 R23.1@1737.45,3410 ; 1737.44,3437.71 R23.1@1737.45,3410 ; 1737.44,3449.46 C27.2@1737.45,3475 ; 1737.44,3500.54 C27.2@1737.45,3475 ; R43.1@2465,2257.44 2528.58,2257.44 2548.58,2277.44 v1(2548.58,2432.6) ; 3920.95,1242.28 C92.2@3940,1242.28 ; 3940,1224.22 C92.2@3940,1242.28 ; 3959.05,1242.28 C92.2@3940,1242.28
  L3_SIG w20: CN4.15@4625,4030.71 CN4.6@4703.75,3951.97
  L4_VCC w40: CN4.15@4625,4030.71 4625,4070 ; 4703.75,3863.75 CN4.6@4703.75,3926.26
  Bottom Layer w5: 1561.69,946.69 U43.3@1577.72,946.69 1577.71,932.71 1575,930 ; 1567.29,972.29 U43.4@1577.72,972.28 1577.71,987.29
  Bottom Layer w20: v1(749.68,1709.68) 749.68,1680.83 ; 770,1680.83 765.83,1680.83 ; v1(785,1700) 765.83,1680.83 ; v1(800,1670) 760,1670 ; U47.5@921.3,1823.11 977.87,1823.11 C190.2@980.28,1825.51 v1(980.27,1790.27) ; 1559.22,900 C173.2@1577.29,900 ; 1577.28,880.95 C173.2@1577.29,900 ; 1577.28,919.05 C173.2@1577.29,900 ; v1(2548.58,2432.6) 2548.58,2968.58 2840,3260 2840,3635 ; C199.2@2750,3575 2780,3575 2840,3635 ; v1(2840,3670) 2840,3635 ; 4063.12,607.01 TP4.1@4110.51,607.01 ; 4079.5,275 JP2.6@4144.61,275 ; 4079.5,375 JP2.4@4144.61,375 ; 4079.5,475 JP2.2@4144.61,475 ; 4110.51,559.62 TP4.1@4110.51,607.01 ; 4110.51,654.4 TP4.1@4110.51,607.01 ; 4144.61,241.39 JP2.6@4144.61,275 ; 4144.61,308.61 JP2.6@4144.61,275 ; 4144.61,341.39 JP2.4@4144.61,375 ; 4144.61,408.61 JP2.4@4144.61,375 ; 4144.61,441.39 JP2.2@4144.61,475 ; 4144.61,508.61 JP2.2@4144.61,475 ; 4157.9,607.01 TP4.1@4110.51,607.01 ; 4206.47,606.64 R129.1@4227.1,606.64 ; 4209.72,275 JP2.6@4144.61,275 ; 4209.72,375 JP2.4@4144.61,375 ; 4209.72,475 JP2.2@4144.61,475 ; 4227.09,578.93 R129.1@4227.1,606.64 ; 4227.09,634.35 R129.1@4227.1,606.64 ; D2.1@4605.51,1589.14 v1(4605.51,1626.69) ; R113.2@4926.69,1324.14 v1(4926.69,1361.69) ; v1(5285,2735) CN8.5@5372.5,2735 ; 749.68,1680.32 760,1670 ; 749.68,1680.32 749.68,1670 760,1670 ; 749.68,1680.32 749.68,1680.83 ; 749.68,1680.83 765.83,1680.83 ; 760,1670 760,1675 765.83,1680.83
  other v1: 4010,582.4 4040,582.4 4010,610 4040,610 4010,640 4040,640 1520,890 1545,890 1520,920 1545,920 3925,1180 3955,1180 3985,1180 3925,1205 3955,1205 3985,1205 1460.16,2175 1485.16,2175 1460.16,2210 1485.16,2210 1585,3400 1585,3430 1584.6,3488.3 1584.6,3518.3 2875,3670 2905,3670
5V_STLK: C123.2 C129.2 JP2.1 R124.1 U18.1 U20.5 U20.6 | length 487.3
  Bottom Layer w10: U20.6@4595.83,327.01 4595.82,290.7 4596.62,289.9 4596.62,288.38 4624.69,260.31 4624.69,212.6 R124.1@4627.28,210 ; 4635,325 4617.52,325 U20.5@4615.51,327.01 4615.51,314.49 4622.56,307.44 C129.2@4670,307.44 4650.43,327.01
  Bottom Layer w20: JP2.1@4345.4,475 v1(4426,475) ; 4892.4,273.08 U18.1@4892.41,306.69 ; 4892.4,340.3 U18.1@4892.41,306.69 ; 4912.23,306.69 U18.1@4892.41,306.69 ; 4912.56,199.46 C123.2@4912.56,225 ; 4912.56,250.54 C123.2@4912.56,225 ; 4933.18,225 C123.2@4912.56,225
  other v1: 4945,178.84 4975,178.84 4946,212 4974,212 4974,240 4946,242 4746.69,251.24 4721.69,252.24 4747,278 4722,279 4747,306 4722,307 4426,448 4451,448 4451,475 4427,501 4452,501
5V_USB_SNK: JP2.3 SB46.1 | length 142.7
  Bottom Layer w20: SB46.1@1014.69,1665 1030,1665 ; v1(1025,1705) 1025,1670 ; v1(1060,1695) 1035,1670 1025,1670 ; v1(1070,1665) 1030,1665 ; 1025,1670 1030,1665
  other v1: 4430,335 4460,335 4430,365
5V_VIN: C134.2 JP2.5 R111.2 U21.2 U21.4 | length 3975.1
  Top Layer w20: v1(4360,1682.5) 4360,298 4383,275 v1(4435,275)
  L3_SIG w20: v1(4260,2270) 4260,1780 4357.5,1682.5 v1(4360,1682.5) ; v1(4260,2300) 4325,2365 4485,2365 5050,2930 v1(5050,3135)
  Bottom Layer w20: 4197.45,2386.7 C134.2@4233.03,2386.69 ; 4233.03,2360.96 C134.2@4233.03,2386.69 ; 4268.61,2386.7 C134.2@4233.03,2386.69 ; 4340.09,2289.49 U21.4@4417.02,2289.49 ; JP2.5@4345.4,275 v1(4435,275) ; 4379.46,2539.49 U21.2@4417.02,2539.49 ; 4417.01,2248.99 U21.4@4417.02,2289.49 ; 4417.01,2329.99 U21.4@4417.02,2289.49 ; 4417.01,2498.99 U21.2@4417.02,2539.49 ; 4417.01,2579.99 U21.2@4417.02,2539.49 ; 4454.56,2539.49 U21.2@4417.02,2539.49 ; 4493.93,2289.49 U21.4@4417.02,2289.49 ; v1(5050,3135) R111.2@5092.29,3135
ARD_A0: SB47.1 SB49.2 TP21.1 U27.R8 | length 8900
  Top Layer w5: v2(2098.02,1907) 2098.02,1984.53 2132,2018.51 2132,2251.66 2110,2273.66 2110,2693.22 2491.78,3075 3658.78,3075 3963.78,3380 4430,3380 v1(4514,3296) 4560,3250 4560,2969 4570,2959 4602,2959
  L3_SIG w4: v1(720,1130) 650,1200 650,2545 760,2655 760,3305 870,3415 1444.5,3415 1732.2,3127.3 1732.2,3087.2 1800,3019.4 1800,2592.5 1895,2497.5 1895,2405 2009.01,2290.99 2009.01,1901.57 2023.38,1887.2 2049.82,1887.2 2052.12,1889.5 2080.52,1889.5 v2(2098.02,1907)
  Bottom Layer w5: v1(720,1130) 725,1125 SB47.1@770.33,1125 ; v2(2098.02,1907) 2098.02,1906.67 2113.7,1890.99 U27.R8@2113.85,1890.99 ; v1(4514,3296) 4560,3250 TP21.1@4560,3245
ARD_A0D: SB23.1 U27.E12 | length 3236.1
  Top Layer w5: v1(3263,2190) 3566,2190 3601,2155 4755,2155 v1(4865,2265)
  L3_SIG w4: v2(2255.1,1560.76) 2255.38,1560.48 2291.48,1560.48 2308.8,1577.8 2324.32,1577.8 2332.52,1586 2332.52,1587.52 2335,1590 2335,1601 2343,1609 2379,1609 2401,1631 2527,1631 2706,1810 3004.95,1810 3026.95,1832 3103,1832 3262,1991 3262,2132 3263,2133 v1(3263,2190)
  Bottom Layer w5: U27.E12@2239.84,1576.03 v2(2255.1,1560.76) ; v1(4865,2265) SB23.1@5025.33,2265
ARD_A0R: CN7.1 R89.1 SB23.2 | length 1215.8
  Top Layer w5: R89.1@4707.72,3015 4780,2942.72 4780,2788.78 4785,2783.78 4785,2780 5068.62,2496.38 v1(5068.62,2310)
  Bottom Layer w5: v1(5068.62,2310) SB23.2@5068.64,2265 5098.63,2235 CN7.1@5372.5,2235
ARD_A1: U8.6 U8.7 U27.P7 | length 3909.4
  Top Layer w5: 2081,1900.67 2081,1894 v2(2098.93,1876.07) ; 2081.01,1900.68 2081.01,1912.7 2081,1983.29 2117,2019.29 2117,2245.44 2095,2267.44 2095,2700.15 2484.85,3090 3651.85,3090 3956.85,3395 4605,3395 4647.2,3352.8 U8.7@4647.2,3293.66 4647.2,3252.8 4655,3245 4665,3245 4672.8,3252.8 U8.6@4672.8,3293.66
  Bottom Layer w5: U27.P7@2082.35,1859.49 v2(2098.93,1876.07)
ARD_A1D: SB22.1 U27.A8 | length 3571.2
  Top Layer w5: v1(3725,2120) 4930,2120 v1(4945,2135)
  L3_SIG w4: v2(2113.78,1427.34) 2137.66,1427.34 2168,1397 2168,1386 2319,1235 2684,1235 2719.59,1270.59 3179.4,1270.59 3725,1816.19 v1(3725,2120)
  Bottom Layer w5: v2(2113.78,1427.34) 2113.85,1427.41 U27.A8@2113.85,1450.04 ; v1(4945,2135) SB22.1@5025.33,2135
ARD_A1R: CN7.2 R92.1 SB22.2 | length 1356.1
  Top Layer w5: R92.1@4795,3192.28 4795,2795 5088.62,2501.38 5088.62,2230 v1(5068.62,2210)
  Bottom Layer w5: SB22.2@5068.64,2135 v1(5068.62,2210) ; SB22.2@5068.64,2135 CN7.2@5237.5,2135
ARD_A2: SB51.2 TP22.1 U27.R7 | length 3809.9
  Top Layer w5: v2(2066.51,1906.69) 2066.51,1982.72 2102,2018.21 2102,2239.22 2080,2261.22 2080,2706.37 2478.63,3105 3645.63,3105 3955.63,3415 v1(4425,3415)
  Bottom Layer w5: v2(2066.51,1906.69) 2082.21,1890.99 U27.R7@2082.35,1890.99 ; SB51.2@4390,3243.62 4390,3300 4413.3,3323.3 4413.3,3403.3 v1(4425,3415) 4542,3415 TP22.1@4558,3399
ARD_A2D: SB21.1 SB41.2 U27.B12 | length 5459.3
  Top Layer w5: v1(3805,2035) v1(4940,2035)
  L3_SIG w4: v1(5265,1490) 5265,880 5320,825 5385,825 5445.54,764.46 5473.79,764.46 5515,723.25 v1(5515,670)
  Bottom Layer w5: U27.B12@2239.84,1481.54 U27.B12@2239.84,1481.54 2222.92,1464.69 2222.92,1334.52 2280,1277.44 2280,1253.78 2438.78,1095 2722.56,1095 2782.56,1035 3020.66,1035 3805,1819.34 v1(3805,2035) ; SB21.1@5025.33,2035 v1(4940,2035) 4920,2035 4895,2010 4895,1825 5230,1490 v1(5265,1490) ; v1(5515,670) 5500,655 5500,630 5510,620 SB41.2@5546.69,620
ARD_A2R: CN7.3 R85.1 SB21.2 | length 1562.5
  Top Layer w5: R85.1@4432.72,3015 4487.72,2960 4513.78,2960 4995,2478.78 4995,2200 5068.62,2126.38 v1(5068.62,2071.38)
  Bottom Layer w5: SB21.2@5068.64,2035 v1(5068.62,2071.38) ; SB21.2@5068.64,2035 CN7.3@5372.5,2035
ARD_A3: U7.6 U7.7 U27.U7 | length 3623.8
  Top Layer w5: v1(4265,3345) 4367.2,3345 4377.2,3335 U7.7@4377.2,3293.66 4377.2,3252.8 4385,3245 4395,3245 4402.8,3252.8 U7.6@4402.8,3293.66
  Bottom Layer w5: U27.U7@2082.35,1953.98 2082.35,1970.74 2129.95,2018.34 2130.03,2215.26 2130.03,2253.69 2250.22,2373.88 2250.86,2373.88 2252.78,2375.8 2624.7,2375.8 2727.8,2478.9 2727.8,2851.46 2831.34,2955 3745,2955 3790,2910 4010,2910 4040,2940 4040,3265 4105,3330 4250,3330 v1(4265,3345)
ARD_A3D: SB20.1 U27.G14 | length 3069.4
  Top Layer w5: v1(3225,2100) 3315,2010 4875,2010 v1(4950,1935)
  L3_SIG w4: v2(2318.52,1623.29) 2318.52,1633.52 2334,1649 2334,1661 2343,1670 2525,1670 2689,1834 2994.96,1834 3071.96,1911 3141,1911 3225,1995 v1(3225,2100)
  Bottom Layer w5: U27.G14@2302.83,1639.02 v2(2318.52,1623.29) ; v1(4950,1935) SB20.1@5025.33,1935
